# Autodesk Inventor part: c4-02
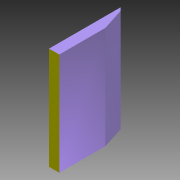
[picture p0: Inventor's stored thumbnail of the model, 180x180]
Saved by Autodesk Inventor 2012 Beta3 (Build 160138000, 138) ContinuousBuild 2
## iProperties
Created: 2010-11
Part Number: c4-02
Material: Default
Document SubType Name: Modeling
Designer: Beta-8540w
Density: 1 g/cm^3
Author: Beta-8540w
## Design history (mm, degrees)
sketch "Sketch1"
  geometry: L1 (0, 0)-(10, 0); L2 (10, 0)-(10, 70); L3 (10, 70)-(0, 70); L4 (0, 70)-(0, 0); L5 (3, 67)-(10, 45); L6 (0, 70)-(3, 67); 1 further point
  constraints: 12 end point, 2 parallel, 2 point on line, 1 horizontal, 1 perpendicular
  dimensions: "d0" = 10 distance of L3.end L2.end; "d1" = 70 distance of L2.end L1.end; "d3" = 25 vertical distance of point (2.045, 70) L5.end; "d6" = 45 deg angle of L4 L6; "d7" = 3 distance from line of L4 L5.start
extrude "Extrusion1" new body sketch "Sketch1" stored distance "d4" = 100; taper "d5" = 0 deg
body "Solid1"
